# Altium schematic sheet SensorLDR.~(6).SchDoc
size A
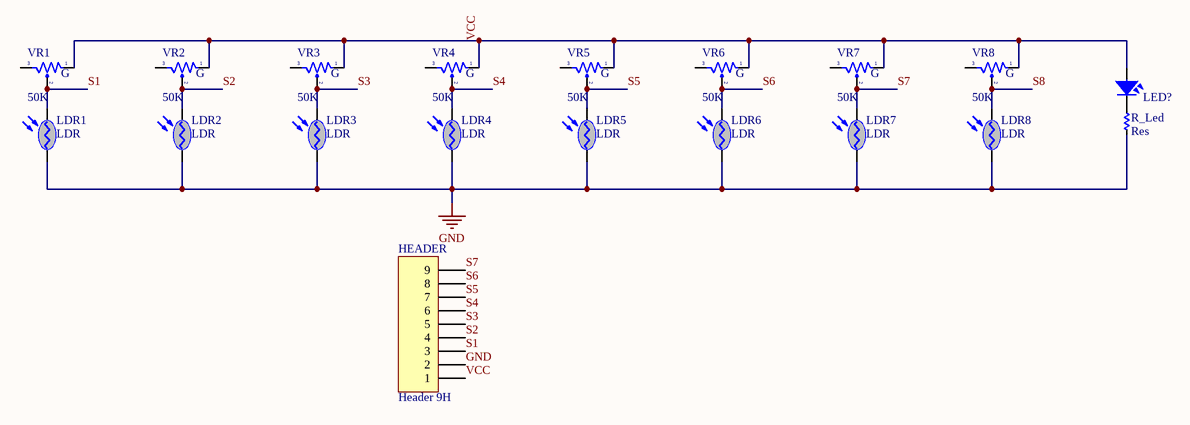
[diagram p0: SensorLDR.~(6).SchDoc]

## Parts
HEADER  Header 9H  [HDR1X9H]
LDR1  LDR  [CDS]
LDR2  LDR  [CDS]
LDR3  LDR  [CDS]
LDR4  LDR  [CDS]
LDR5  LDR  [CDS]
LDR6  LDR  [CDS]
LDR7  LDR  [CDS]
LDR8  LDR  [CDS]
LED?  LED  [LED-3MM-YELLOW]  (value not drawn)
R_Led  Res  [RES-1/2W]
VR1  50K  [VR-S2]
VR2  50K  [VR-S2]
VR3  50K  [VR-S2]
VR4  50K  [VR-S2]
VR5  50K  [VR-S2]
VR6  50K  [VR-S2]
VR7  50K  [VR-S2]
VR8  50K  [VR-S2]

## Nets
GND: HEADER.2 LDR1.1(A) LDR2.1(A) LDR3.1(A) LDR4.1(A) LDR5.1(A) LDR6.1(A) LDR7.1(A) LDR8.1(A) R_Led.2
S1: HEADER.3 LDR1.2(K) VR1.2
S2: HEADER.4 LDR2.2(K) VR2.2
S3: HEADER.5 LDR3.2(K) VR3.2
S4: HEADER.6 LDR4.2(K) VR4.2
S5: HEADER.7 LDR5.2(K) VR5.2
S6: HEADER.8 LDR6.2(K) VR6.2
S7: HEADER.9 LDR7.2(K) VR7.2
S8: LDR8.2(K) VR8.2
VCC: HEADER.1 LED?.1 VR1.1 VR2.1 VR3.1 VR4.1 VR5.1 VR6.1 VR7.1 VR8.1
NetLED?_2: LED?.2 R_Led.1

Not connected (* = marked no-connect by the designer): VR1 3; VR2 3; VR3 3; VR4 3; VR5 3; VR6 3; VR7 3; VR8 3

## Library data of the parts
HEADER = Header 9H: Header, 9-Pin, Right Angle
LDR1-LDR8 = LDR: Quang Tro
LED? = LED: LED Single colour Green and Red; Value: LED 3 ly Single Colour
R_Led = Res: Manufacturer: Generic Components; Class: Passive; SubClass: R
VR1-VR8 = VR-S: Var Resistor; Value: Volume 50k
